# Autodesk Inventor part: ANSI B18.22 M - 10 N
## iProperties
Comments: To add or edit properties for Autodesk Inventor files, use iProperties.
Created: 2004-08
Part Number: ANSI B18.22 M - 10 N
Vendor: Autodesk Inc.
Document SubType Name: Modeling
Designer: John Blackburn
Material: Default
Description: Plain Washer
Standard: ANSI B18.22 M
Alert: To add or edit properties for Autodesk Inventor files, use iProperties.
Control State: 0
Master: False
Checked Out: False
Shininess: 64.0
Length Units: 11269
Angle Units: 11279
Time Units: 11290
Mass Units: 11283
Length Display Precision: 3
Angle Display Precision: 2
Compacted: True
Classification: un/spsc 31161807
Density: 0.0
Volumn: 0.0
Area: 0.0
PropertySet Name: Model Information
Author: John Blackburn
Revision Number: 8
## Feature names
1. Body [Extrusion]
